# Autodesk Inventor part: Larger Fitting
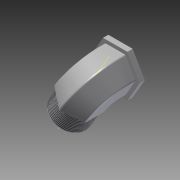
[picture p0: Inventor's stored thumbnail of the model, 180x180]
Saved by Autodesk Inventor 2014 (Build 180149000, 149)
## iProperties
Company: Autodesk, Inc.
Shininess: 64.0
Length Units: 11272
Angle Units: 11279
Time Units: 11290
Mass Units: 11286
Length Display Precision: 3
Angle Display Precision: 2
Compacted: True
Part Number: Larger Fitting
Document SubType Name: Modeling
Created: 2003-10
Designer: Autodesk, Inc.
Manufacturer: Standard
Standards Organization: Custom
Density: 8.03 g/cm^3
Material: Stainless Steel, Austenitic
Mass: 1346.74 g
Surface Area: 484.305 cm^2
Volume: 167.713 cm^3
Appearance: Steel
Density: 0.0
Volumn: 0.0
Area: 0.0
PropertySet Name: Model Information
Control State: 0
Master: False
Checked Out: False
Author: Autodesk, Inc.
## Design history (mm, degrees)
sketch "Sketch1"
  geometry: L1 (43.994, 0)-(21.997, -38.1); L2 (21.997, -38.1)-(-21.997, -38.1); L3 (-21.997, -38.1)-(-43.994, 0); L4 (-43.994, 0)-(-21.997, 38.1); L5 (-21.997, 38.1)-(21.997, 38.1); L6 (21.997, 38.1)-(43.994, 0); C1 r 25.4 at (0, 0); 1 further point
  constraints: 12 end point, 1 centre point, 1 coincident, 11 other
  dimensions: "d0" = 76.2 distance between parallel lines of L2 L5
extrude "Extrusion1" new body sketch "Sketch1" distance "d1" = 9.525; taper "d2" = 0 deg
sketch "Sketch2"
  geometry: L1 (-21.997, 38.1)-(21.997, 38.1) reference; L2 (18.331, 31.75)-(36.662, 0); L3 (36.662, 0)-(18.331, -31.75); L4 (18.331, -31.75)-(-18.331, -31.75); L5 (-18.331, -31.75)-(-36.662, 0); L6 (-36.662, 0)-(-18.331, 31.75); L7 (-18.331, 31.75)-(18.331, 31.75); C1 r 25.4 at (0, 0) reference; 1 further point
  constraints: 12 end point, 1 coincident, 1 parallel, 11 other
  dimensions: "d3" = 63.5 distance between parallel lines of L4 L7
extrude "Extrusion2" join sketch "Sketch2" distance "d4" = 9.525; taper "d5" = 0 deg
sketch "Sketch3"
  geometry: L1 (36.662, 0)-(18.331, -31.75) reference; L2 (18.331, 31.75)-(36.662, 0) reference; L3 (-18.331, 31.75)-(18.331, 31.75) reference; L4 (-36.662, 0)-(-18.331, 31.75) reference; L5 (-18.331, -31.75)-(-36.662, 0) reference; L6 (18.331, -31.75)-(-18.331, -31.75) reference; L7 (-18.331, -31.75)-(-80.94, 4.397); L8 (-18.331, -31.75)-(12.465, -49.53); C1 r 25.4 at (0, 0) reference
  constraints: 4 end point, 1 collinear
  dimensions: "d6" = 30 deg angle of L7 L5
revolve "Revolution1" sketch "Sketch3" stored, may be unused: angle "d7" = 90 deg
sketch "Sketch4"
  geometry: L1 (-31.75, 54.993)-(0, 36.662) reference; C1 r 25.4 at (-31.75, 18.331) reference; C2 r 31.75 at (-31.75, 18.331)
  constraints: 1 centre point, 1 coincident, 1 tangent
extrude "Extrusion3" join sketch "Sketch4" distance "d8" = 38.1; taper "d9" = 0 deg
chamfer "Chamfer1" distance "d10" = 5.08; stored, may be unused: second distance "d11" = 3.175, angle "d12" = 45 deg
thread "Thread1" dims "d13" = 25.4, "d14" = 0
fillet "Fillet1" dims "d15" = 3.175
workaxis "Work Axis1"
body "Solid1"
other parameters: "d16" = 0
